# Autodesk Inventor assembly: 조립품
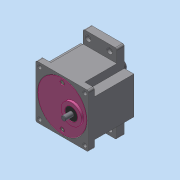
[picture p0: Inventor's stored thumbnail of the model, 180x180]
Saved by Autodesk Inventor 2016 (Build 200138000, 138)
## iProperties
Created: 2020-08
Part Number: 조립품
Material: 일반
Document SubType Name: Assembly
Designer: User
Author: User
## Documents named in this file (10)
- C:\Users\User\Desktop\700815V1008\조립품.iam
- C:\Users\User\Desktop\700815V1008\메인 축.ipt
- C:\Users\User\Desktop\700815V1008\베어링 608.ipt
- C:\Users\User\Desktop\700815V1008\베어링 6003.ipt
- C:\Users\User\Desktop\700815V1008\본체.ipt
- C:\Users\User\Desktop\700815V1008\볼트 M4.ipt
- C:\Users\User\Desktop\700815V1008\서브 축.ipt
- C:\Users\User\Desktop\700815V1008\오일 실 8 22 7.ipt
- C:\Users\User\Desktop\700815V1008\오일 실 17 32 8.ipt
- C:\Users\User\Desktop\700815V1008\커버.ipt
